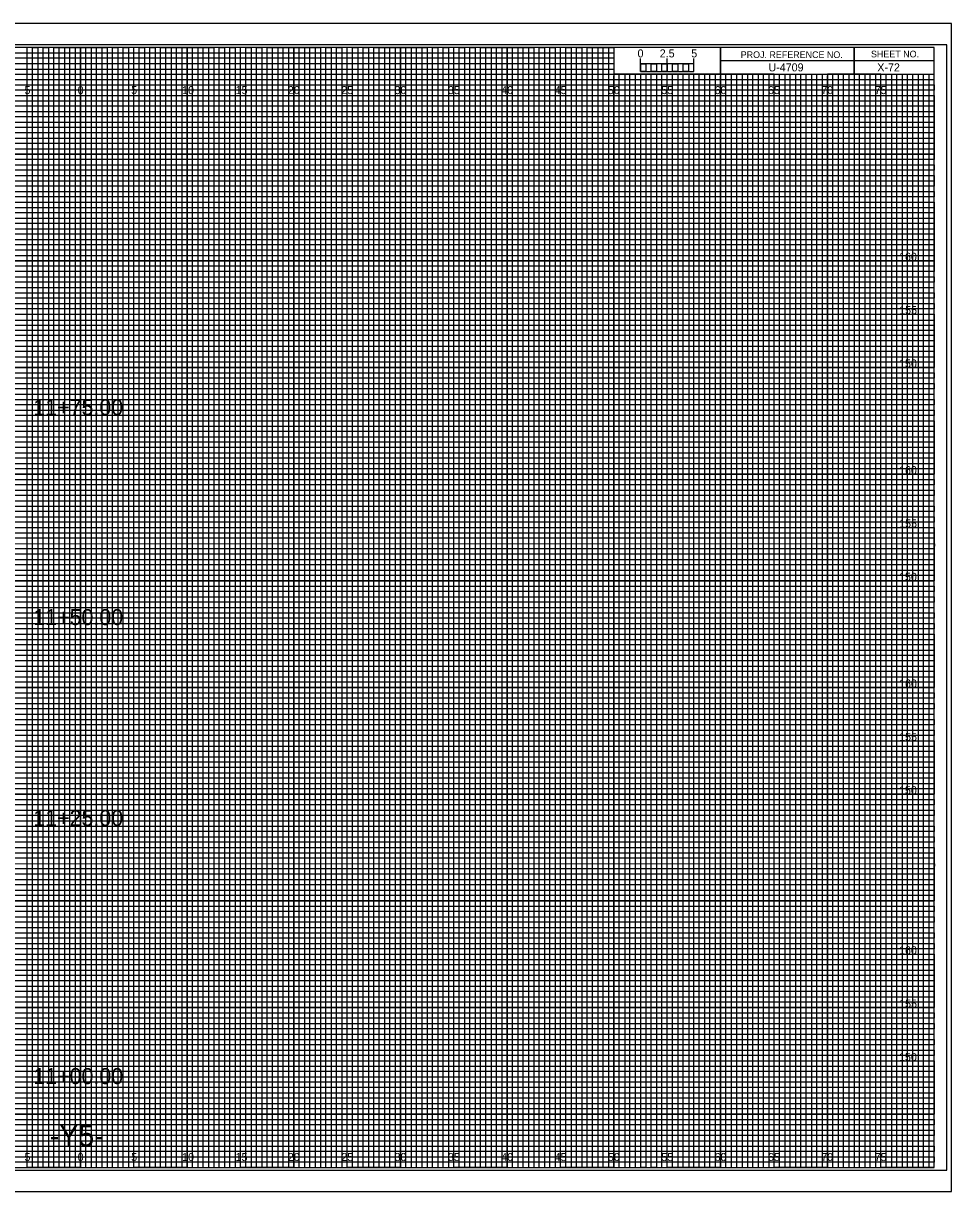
# Model space of a CAD drawing. Extents: x -7 to 162, y 108 to 217.
# Drawn here: x 74.6 to 161.7, y 107.7 to 217.2 of the extents above; entities that cross this region are included whole.
import ezdxf

# ---------------------------------------------------------------- set-up
doc = ezdxf.new("R2010")
doc.units = 0
for name, color, linetype in [('Prop CMT Shear Line', 7, 'Continuous'), ('Prop XS Alignment Label', 7, 'Continuous'), ('Prop XS Bar Scale Labels', 7, 'Continuous'), ('Prop XS Earthwork Shape', 7, 'Continuous'), ('Prop XS Elevation Labels', 7, 'Continuous'), ('Prop XS Project Number', 7, 'Continuous'), ('Prop XS Sheet Number', 7, 'Continuous'), ('Prop XS Station Labels', 7, 'Continuous'), ('Scratch_Level_1', 7, 'Continuous'), ('Sheet Cross Section CELL', 7, 'Continuous'), ('Sheet Cross Section Grid Minor 1 CELL', 7, 'Continuous'), ('Sheet Cross Section Grid Minor 2 CELL', 7, 'Continuous'), ('Sheet Cross Section Scale CELL', 7, 'Continuous'), ('Sheet Cutting Line CELL', 7, 'Continuous'), ('Sheet DOT Grid CELL', 7, 'Continuous'), ('Sheet Plot Border Inside CELL', 7, 'Continuous'), ('Sheet Plot Border Outside CELL', 7, 'Continuous')]:
    doc.layers.add(name, color=color, linetype=linetype)

msp = doc.modelspace()

# ---------------------------------------------------------------- linework, layer by layer
at = {"layer": 'Prop CMT Shear Line'}
for p, q in [((75, 215), (70, 215)), ((75, 110), (75, 215)), ((85, 215), (80, 215)), ((80, 215), (80, 110)), ((85, 110), (85, 215)), ((95, 215), (90, 215)), ((90, 215), (90, 110)), ((95, 110), (95, 215)), ((105, 215), (100, 215)), ((100, 215), (100, 110)), ((105, 110), (105, 215)), ((115, 215), (110, 215)), ((110, 215), (110, 110)), ((115, 110), (115, 215)), ((125, 215), (120, 215)), ((120, 215), (120, 110)), ((125, 110), (125, 215)), ((130, 215), (130, 110)), ((135, 110), (135, 212.5)), ((145, 212.5), (140, 212.5)), ((140, 212.5), (140, 110)), ((145, 110), (145, 212.5)), ((155, 212.5), (150, 212.5)), ((150, 212.5), (150, 110)), ((155, 110), (155, 212.5)), ((80, 110), (75, 110)), ((90, 110), (85, 110)), ((100, 110), (95, 110)), ((110, 110), (105, 110)), ((120, 110), (115, 110)), ((130, 110), (125, 110)), ((140, 110), (135, 110)), ((150, 110), (145, 110)), ((160, 110), (155, 110)), ((160, 110), (160, 110))]:
    msp.add_line(p, q, dxfattribs=at)
for points in [[(0, 210), (160, 210), (160, 205), (0, 205)], [(0, 200), (160, 200), (160, 195), (0, 195)], [(0, 190), (160, 190), (160, 185), (0, 185)], [(0, 180), (160, 180), (160, 175), (0, 175)], [(0, 170), (160, 170), (160, 165), (0, 165)], [(0, 160), (160, 160), (160, 155), (0, 155)], [(0, 150), (160, 150), (160, 145), (0, 145)], [(0, 140), (160, 140), (160, 135), (0, 135)], [(0, 130), (160, 130), (160, 125), (0, 125)], [(0, 120), (160, 120), (160, 115), (0, 115)]]:
    msp.add_lwpolyline(points, dxfattribs=at)
at = {"layer": 'Prop XS Earthwork Shape'}
for points in [[(72.5, 110), (77.5, 110), (77.5, 215), (82.5, 215), (82.5, 110), (87.5, 110), (87.5, 215), (92.5, 215), (92.5, 110), (97.5, 110), (97.5, 215), (102.5, 215), (102.5, 110), (107.5, 110), (107.5, 215), (112.5, 215), (112.5, 110), (117.5, 110), (117.5, 215), (122.5, 215), (122.5, 110), (127.5, 110), (127.5, 215), (129.97, 215), (130, 215), (130, 212.5), (132.5, 212.5), (132.5, 110), (137.5, 110), (137.5, 212.5), (142.5, 212.5), (142.5, 110), (147.5, 110), (147.5, 212.5), (152.5, 212.5), (152.5, 110), (157.5, 110), (157.5, 212.5)], [(0, 212.5), (137.5, 212.5)], [(0, 202.5), (160, 202.5), (160, 207.5), (0, 207.5)], [(0, 192.5), (160, 192.5), (160, 197.5), (0, 197.5)], [(0, 182.5), (160, 182.5), (160, 187.5), (0, 187.5)], [(0, 172.5), (160, 172.5), (160, 177.5), (0, 177.5)], [(0, 162.5), (160, 162.5), (160, 167.5), (0, 167.5)], [(0, 152.5), (160, 152.5), (160, 157.5), (0, 157.5)], [(0, 142.5), (160, 142.5), (160, 147.5), (0, 147.5)], [(0, 132.5), (160, 132.5), (160, 137.5), (0, 137.5)], [(0, 122.5), (160, 122.5), (160, 127.5), (0, 127.5)], [(0, 112.5), (160, 112.5), (160, 117.5), (0, 117.5)]]:
    msp.add_lwpolyline(points, dxfattribs=at)
at = {"layer": 'Sheet Cross Section CELL'}
for p, q in [((152.5, 215), (152.5, 212.5)), ((152.5, 212.5), (152.5, 215)), ((160, 213.75), (140, 213.75)), ((140, 213.75), (140, 212.5)), ((140, 212.5), (160, 212.5))]:
    msp.add_line(p, q, dxfattribs=at)
for points in [[(160, 215), (0, 215), (0, 110), (160, 110)], [(140, 215), (130, 215), (130, 212.52), (140, 212.52)], [(160, 215), (140, 215), (140, 212.5), (160, 212.5)]]:
    msp.add_lwpolyline(points, close=True, dxfattribs=at)
at = {"layer": 'Sheet Cross Section Grid Minor 1 CELL'}
for p, q in [((0, 214.5), (130, 214.5)), ((130, 213.99), (0, 213.99)), ((130, 214.5), (130, 213.99)), ((0, 213.5), (130, 213.5)), ((130, 212.94), (0, 212.94)), ((130, 213.5), (130, 212.94)), ((0, 212), (160, 212))]:
    msp.add_line(p, q, dxfattribs=at)
for points in [[(0, 211.5), (135, 211.5), (160, 211.5), (160, 211), (0, 211)], [(0, 210.5), (160, 210.5), (160, 209.5), (0, 209.5)], [(0, 209), (160, 209), (160, 208.5), (0, 208.49)], [(0, 208), (160, 208), (160, 207), (0, 207)], [(0, 206.5), (160, 206.5), (160, 206), (0, 206)], [(0, 205.5), (160, 205.5), (160, 204.5), (0, 204.5)], [(0, 204), (160, 204), (160, 203.5), (0, 203.5)], [(0, 203), (160, 203), (160, 202), (0, 202)], [(0, 201.5), (160, 201.5), (160, 201), (0, 201)], [(0, 200.5), (160, 200.5), (160, 199.5), (0, 199.5)], [(0, 199), (160, 199), (160, 198.5), (0, 198.5)], [(0, 198), (160, 198), (160, 196.97), (160, 196.5), (160, 196), (0, 196)], [(0, 197), (160, 197), (160, 196.5), (0, 196.5)], [(0, 195.5), (160, 195.5), (160, 194.5), (0, 194.52)], [(0, 194.52), (160, 194.5), (160, 194), (0, 194)], [(0, 193.5), (160, 193.5), (160, 193), (0, 193)], [(0, 192), (160, 192), (160, 191.5), (0, 191.5)], [(0, 191), (160, 191), (160, 190.5), (0, 190.5)], [(-0.04, 189.44), (160, 189.44), (160, 188.94), (-0.04, 188.94)], [(0, 188.5), (160, 188.5), (160, 188), (0, 188)], [(0, 187), (160, 187), (160, 186.5), (0, 186.5)], [(0, 186), (160, 186), (160, 185.5), (0, 185.5)], [(0, 184.5), (160, 184.5), (160, 184), (0, 184)], [(0, 183.5), (160, 183.5), (160, 183), (0, 183)], [(0, 182), (160, 182), (160, 181.5), (0, 181.5)], [(0, 181), (160, 181), (160, 180.5), (0, 180.5)], [(0, 179.5), (160, 179.5), (160, 178.99), (0, 179)], [(0, 178.5), (160, 178.5), (160, 178), (0, 178)], [(0, 177), (160, 177), (160, 176.5), (0, 176.5)], [(0, 176), (160, 176), (160, 175.5), (0, 175.5)], [(0, 174.5), (160, 174.5), (160, 174), (0, 174)], [(0, 173.5), (160, 173.5), (160, 173), (0, 173)], [(0, 172), (160, 172), (160, 171.5), (0, 171.5)], [(0, 171), (160, 171), (160, 170.5), (0, 170.5)], [(0, 169.5), (160, 169.5), (160, 169), (0, 169)], [(0, 168.5), (160.03, 168.46), (160, 168), (0, 168)], [(0, 167), (160, 167), (160, 166.5), (0, 166.5)], [(0, 166), (160, 166), (160, 165.5), (0, 165.5)], [(0, 164.5), (160, 164.5), (160, 164), (0, 164)], [(0, 163.5), (160, 163.5), (160, 163), (0, 163)], [(0, 162), (160, 162), (160, 161.5), (0, 161.5)], [(0, 161), (160, 161), (160, 160.5), (0, 160.5)], [(0, 159.5), (160, 159.5), (160, 159), (0, 159)], [(0, 158.5), (160, 158.5), (160, 158), (0, 158)], [(0, 157), (160, 157), (160, 156.5), (0, 156.5)], [(0, 156), (160, 156), (160, 155.5), (0, 155.5)], [(0, 154.5), (160, 154.5), (160, 154), (0, 154)], [(0, 153.5), (160, 153.5), (160, 153), (0, 153)], [(0, 152), (160, 152), (160, 151.5), (0, 151.5)], [(0, 151), (160, 151), (160, 150.5), (0, 150.5)], [(0, 149.5), (160, 149.5), (160, 148.99), (0, 149)], [(0, 148.5), (160, 148.5), (160, 148), (0, 148)], [(0, 147), (160, 147), (160, 146.5), (0, 146.5)], [(0, 146), (160, 146), (160, 145.5), (0, 145.5)], [(0, 144.5), (160, 144.5), (160, 144), (0, 144)], [(0, 143.5), (160, 143.5), (160, 143), (0, 143)], [(0, 142), (160, 142), (160, 141.5), (0, 141.5)], [(0, 141), (160, 141), (160, 140.5), (0, 140.5)], [(0, 139.5), (160, 139.5), (160, 139), (0, 139)], [(0, 138.5), (160.03, 138.46), (160, 138), (0, 138)], [(0, 137), (160, 137), (160, 136.5), (0, 136.5)], [(0, 136), (160, 136), (160, 135.5), (0, 135.5)], [(0, 134.5), (160, 134.5), (160, 134), (0, 134)], [(0, 133.5), (160, 133.5), (160, 133), (0, 133)], [(0, 132), (160, 132), (160, 131.5), (0, 131.5)], [(0, 131), (160, 131), (160, 130.5), (0, 130.5)], [(0, 129.5), (160, 129.5), (160, 129), (0, 129)], [(0, 128.5), (160, 128.5), (160, 128), (0, 128)], [(0, 127), (160, 127), (160, 126.5), (0, 126.5)], [(0, 126), (160, 126), (160, 125.5), (0, 125.5)], [(0, 124.5), (160, 124.5), (160, 124), (0, 124)], [(0, 123.5), (160, 123.5), (160, 123), (0, 123)], [(0, 122), (160, 122), (160, 121.5), (0, 121.5)], [(0, 121), (160, 121), (160, 120.5), (0, 120.5)], [(0, 119.5), (160, 119.5), (160, 119), (0, 119)], [(0, 118.5), (160, 118.5), (160, 118), (0, 118)], [(0, 117), (160, 117), (160, 116.5), (0, 116.5)], [(0, 116), (160, 116), (160, 115.5), (0, 115.5)], [(0, 114.5), (160, 114.5), (160, 114), (0, 114)], [(0, 113.5), (160, 113.5), (160, 113), (0, 113)], [(0, 112), (160, 112), (160, 111.5), (0, 111.5)], [(0, 111), (160, 111), (160, 110.5), (0, 110.5)]]:
    msp.add_lwpolyline(points, dxfattribs=at)
at = {"layer": 'Sheet Cross Section Grid Minor 2 CELL'}
for p, q in [((133.5, 212.5), (133, 212.5)), ((133, 212.5), (133, 110)), ((133.5, 110), (133.5, 212.5)), ((134.5, 212.5), (134, 212.5)), ((134, 212.5), (134, 110)), ((134.5, 110), (134.5, 212.5)), ((133, 110), (132.5, 110)), ((134, 110), (133.5, 110))]:
    msp.add_line(p, q, dxfattribs=at)
for points in [[(75, 110), (75.5, 110), (75.5, 215), (76, 215), (76, 110)], [(76, 110), (76.5, 110), (76.5, 215), (77, 215), (77, 110)], [(77.5, 110), (78, 110), (78, 215), (78.5, 215), (78.5, 110)], [(78.5, 110), (79, 110), (79, 215), (79.5, 215), (79.5, 110)], [(80, 110), (80.5, 110), (80.5, 215), (81, 215), (81, 110)], [(81, 110), (81.5, 110), (81.5, 215), (82, 215), (82, 110)], [(82.5, 110), (83, 110), (83, 215), (83.5, 215), (83.5, 110)], [(83.5, 110), (84, 110), (84, 215), (84.5, 215), (84.5, 110)], [(85, 110), (85.5, 110), (85.5, 215), (86, 215), (86, 110)], [(86, 110), (86.5, 110), (86.5, 215), (87, 215), (87, 110)], [(87.5, 110), (88, 110), (88, 215), (88.5, 215), (88.5, 110)], [(88.5, 110), (89, 110), (89, 215), (89.5, 215), (89.5, 110)], [(90, 110), (90.5, 110), (90.5, 215), (91, 215), (91, 110)], [(91, 110), (91.5, 110), (91.5, 215), (92, 215), (92, 110)], [(92.5, 110), (93, 110), (93, 215), (93.5, 215), (93.5, 110)], [(93.5, 110), (94, 110), (94, 215), (94.5, 215), (94.5, 110)], [(95, 110), (95.5, 110), (95.5, 215), (96, 215), (96, 110)], [(96, 110), (96.5, 110), (96.5, 215), (97, 215), (97, 110)], [(97.5, 110), (98, 110), (98, 215), (98.5, 215), (98.5, 110)], [(98.5, 110), (99, 110), (99, 215), (99.5, 215), (99.5, 110)], [(100, 110), (100.5, 110), (100.5, 215), (101, 215), (101, 110)], [(101, 110), (101.5, 110), (101.5, 215), (102, 215), (102, 110)], [(102.5, 110), (103, 110), (103, 215), (103.5, 215), (103.5, 110)], [(103.5, 110), (104, 110), (104, 215), (104.5, 215), (104.5, 110)], [(105, 110), (105.5, 110), (105.5, 215), (106, 215), (106, 110)], [(106, 110), (106.5, 110), (106.5, 215), (107, 215), (107, 110)], [(107.5, 110), (108, 110), (108, 215), (108.5, 215), (108.5, 110)], [(108.5, 110), (109, 110), (109, 215), (109.5, 215), (109.5, 110)], [(110, 110), (110.5, 110), (110.5, 215), (111, 215), (111, 110)], [(111, 110), (111.5, 110), (111.5, 215), (112, 215), (112, 110)], [(112.5, 110), (113, 110), (113, 215), (113.5, 215), (113.5, 110)], [(113.5, 110), (114, 110), (114, 215), (114.5, 215), (114.5, 110)], [(115, 110), (115.5, 110), (115.5, 215), (116, 215), (116, 110)], [(116, 110), (116.5, 110), (116.5, 215), (117, 215), (117, 110)], [(117.5, 110), (118, 110), (118, 215), (118.5, 215), (118.5, 110)], [(118.5, 110), (119, 110), (119, 215), (119.5, 215), (119.5, 110)], [(120, 110), (120.5, 110), (120.5, 215), (121, 215), (121, 110)], [(121, 110), (121.5, 110), (121.5, 215), (122, 215), (122, 110)], [(122.5, 110), (123, 110), (123, 215), (123.5, 215), (123.5, 110)], [(123.5, 110), (124, 110), (124, 215), (124.5, 215), (124.5, 110)], [(125, 110), (125.5, 110), (125.5, 215), (126, 215), (126, 110)], [(126, 110), (126.5, 110), (126.5, 215), (127, 215), (127, 110)], [(127.5, 110), (128, 110), (128, 215), (128.5, 215), (128.5, 110)], [(128.5, 110), (129, 110), (129, 215), (129.5, 215), (129.5, 110)], [(130, 110), (130.5, 110), (130.5, 212.5), (131.01, 212.5), (131.01, 110)], [(131, 110), (131.5, 110), (131.5, 212.5), (132, 212.5), (132, 110)], [(135, 110), (135.49, 110), (135.49, 212.5), (136, 212.5), (136, 110)], [(136, 110), (136.5, 110), (136.5, 212.5), (137.03, 212.5), (137.03, 110)], [(137.5, 110), (138, 110), (138, 212.5), (138.5, 212.5), (138.5, 110)], [(138.5, 110), (139, 110), (139, 212.5), (139.5, 212.5), (139.5, 110)], [(140, 110), (140.5, 110), (140.5, 212.5), (141, 212.5), (141, 110)], [(141, 110), (141.5, 110), (141.5, 212.5), (142, 212.5), (142, 110)], [(142.5, 110), (143, 110), (143, 212.5), (143.5, 212.5), (143.5, 110)], [(143.5, 110), (144, 110), (144, 212.5), (144.5, 212.5), (144.5, 110)], [(145, 110), (145.5, 110), (145.5, 212.5), (146, 212.5), (146, 110)], [(146, 110), (146.5, 110), (146.5, 212.5), (147, 212.5), (147, 110)], [(147.5, 110), (148, 110), (148, 212.5), (148.5, 212.5), (148.5, 110)], [(148.5, 110), (149, 110), (149, 212.5), (149.5, 212.5), (149.5, 110)], [(150, 110), (150.5, 110), (150.5, 212.5), (151, 212.5), (151, 110)], [(151, 110), (151.5, 110), (151.5, 212.5), (152, 212.5), (152, 110)], [(152.5, 110), (153, 110), (153, 212.5), (153.5, 212.5), (153.5, 110)], [(153.5, 110), (154, 110), (154, 212.5), (154.5, 212.5), (154.5, 110)], [(155, 110), (155.5, 110), (155.5, 212.5), (156, 212.5), (156, 110)], [(156, 110), (156.5, 110), (156.5, 212.5), (157, 212.5), (157, 110)], [(157.5, 110), (158, 110), (158, 212.5), (158.5, 212.5), (158.5, 110)], [(158.5, 110), (159, 110), (159, 212.5), (159.5, 212.5), (159.5, 110)]]:
    msp.add_lwpolyline(points, dxfattribs=at)
at = {"layer": 'Sheet Cross Section Scale CELL'}
for p, q in [((132.5, 212.75), (132.5, 213.95)), ((132.5, 213.45), (132.5, 213.95)), ((135, 212.75), (135, 213.95)), ((137.5, 212.75), (137.5, 213.95)), ((137.5, 213.45), (137.5, 213.95))]:
    msp.add_line(p, q, dxfattribs=at)
for points in [[(137.5, 213.45), (132.5, 213.45), (132.5, 212.75), (137.5, 212.75)], [(132.5, 213.45), (133, 213.45), (133, 212.75), (132.5, 212.75)], [(133.5, 213.45), (134, 213.45), (134, 212.75), (133.5, 212.75)], [(134.5, 213.45), (135, 213.45), (135, 212.75), (134.5, 212.75)], [(135.5, 213.45), (136, 213.45), (136, 212.75), (135.5, 212.75)], [(136.5, 213.45), (137, 213.45), (137, 212.75), (136.5, 212.75)]]:
    msp.add_lwpolyline(points, close=True, dxfattribs=at)
at = {"layer": 'Sheet Cutting Line CELL'}
for p, q in [((161.65, 217.25), (-6.7, 217.25)), ((-6.7, 107.75), (161.65, 107.75))]:
    msp.add_line(p, q, dxfattribs=at)
at = {"layer": 'Sheet DOT Grid CELL'}
for p, q in [((75, 110), (75, 215)), ((80, 110), (80, 215)), ((85, 110), (85, 215)), ((90, 110), (90, 215)), ((95, 110), (95, 215)), ((100, 110), (100, 215)), ((105, 110), (105, 215)), ((110, 110), (110, 215)), ((115, 110), (115, 215)), ((120, 110), (120, 215)), ((125, 110), (125, 215)), ((130, 110), (130, 212.34)), ((135, 110), (135, 212.34)), ((140, 110), (140, 212.34)), ((145, 110), (145, 212.34)), ((150, 110), (150, 212.34)), ((155, 110), (155, 212.34)), ((0, 210), (160, 210)), ((0, 205), (160, 205)), ((0, 200), (160, 200)), ((0, 195), (160, 195)), ((0, 190), (160, 190)), ((0, 185), (160, 185)), ((0, 180), (160, 180)), ((0, 175), (160, 175)), ((0, 170), (160, 170)), ((0, 165), (160, 165)), ((0, 160), (160, 160)), ((0, 155), (160, 155)), ((0, 150), (160, 150)), ((0, 145), (160, 145)), ((0, 140), (160, 140)), ((0, 135), (160, 135)), ((0, 130), (160, 130)), ((0, 125), (160, 125)), ((0, 120), (160, 120)), ((0, 115), (160, 115))]:
    msp.add_line(p, q, dxfattribs=at)
at = {"layer": 'Sheet Plot Border Inside CELL'}
msp.add_lwpolyline([(-5.4, 109.75), (161.2, 109.75), (161.2, 215.25), (-5.4, 215.25)], close=True, dxfattribs=at)
at = {"layer": 'Sheet Plot Border Outside CELL'}
msp.add_lwpolyline([(-6.7, 107.75), (161.65, 107.75), (161.65, 217.25), (-6.7, 217.25)], close=True, dxfattribs=at)

# ---------------------------------------------------------------- texts
at = {"layer": 'Prop XS Alignment Label'}
msp.add_text('-Y5-', height=2, dxfattribs=at).set_placement((77.12, 112))
at = {"layer": 'Prop XS Bar Scale Labels'}
for s, p in [('2.5', (134.29, 214.06)), ('5', (137.24, 214.06))]:
    msp.add_text(s, height=0.75, dxfattribs=at).set_placement(p)
at = {"layer": 'Prop XS Elevation Labels'}
for s, p in [('160', (156.72, 195)), ('155', (156.73, 190)), ('150', (156.72, 185)), ('160', (156.72, 175)), ('155', (156.73, 170)), ('150', (156.72, 165)), ('160', (156.72, 155)), ('155', (156.73, 150)), ('150', (156.72, 145)), ('160', (156.72, 130)), ('155', (156.73, 125)), ('150', (156.72, 120))]:
    msp.add_text(s, height=0.75, dxfattribs=at).set_placement(p)
at = {"layer": 'Prop XS Project Number'}
msp.add_text('U-4709', height=0.75, dxfattribs=at).set_placement((144.48, 212.75))
at = {"layer": 'Prop XS Sheet Number'}
msp.add_text('X-72', height=0.75, dxfattribs=at).set_placement((154.68, 212.75))
at = {"layer": 'Prop XS Station Labels'}
for s, p in [('11+75.00', (75.57, 180.52)), ('11+50.00', (75.57, 160.85)), ('11+25.00', (75.57, 142.02)), ('11+00.00', (75.57, 117.83))]:
    msp.add_text(s, height=1.5, dxfattribs=at).set_placement(p)
at = {"layer": 'Scratch_Level_1'}
for s, p in [('5', (74.74, 210.62)), ('0', (79.73, 210.62)), ('0', (79.73, 210.62)), ('5', (84.74, 210.62)), ('10', (89.52, 210.62)), ('15', (94.53, 210.62)), ('20', (99.43, 210.62)), ('25', (104.44, 210.62)), ('30', (109.43, 210.62)), ('35', (114.44, 210.62)), ('40', (119.43, 210.62)), ('45', (124.44, 210.62)), ('50', (129.43, 210.62)), ('55', (134.44, 210.62)), ('60', (139.43, 210.62)), ('65', (144.44, 210.62)), ('70', (149.43, 210.62)), ('75', (154.44, 210.62)), ('5', (74.74, 110.62)), ('0', (79.73, 110.62)), ('0', (79.73, 110.62)), ('5', (84.74, 110.62)), ('10', (89.52, 110.62)), ('15', (94.53, 110.62)), ('20', (99.43, 110.62)), ('25', (104.44, 110.62)), ('30', (109.43, 110.62)), ('35', (114.44, 110.62)), ('40', (119.43, 110.62)), ('45', (124.44, 110.62)), ('50', (129.43, 110.62)), ('55', (134.44, 110.62)), ('60', (139.43, 110.62)), ('65', (144.44, 110.62)), ('70', (149.43, 110.62)), ('75', (154.44, 110.62))]:
    msp.add_text(s, height=0.75, dxfattribs=at).set_placement(p)
at = {"layer": 'Sheet Cross Section CELL'}
for s, p in [('PROJ. REFERENCE NO.', (141.88, 214)), ('SHEET NO.', (154.09, 214.06))]:
    msp.add_text(s, height=0.625, dxfattribs=at).set_placement(p)
at = {"layer": 'Sheet Cross Section Scale CELL'}
msp.add_text('0', height=0.75, dxfattribs=at).set_placement((132.21, 214.06))

doc.saveas('drawing.dxf')
